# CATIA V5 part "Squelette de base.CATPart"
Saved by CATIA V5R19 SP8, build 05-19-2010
Part number: Squelette de base
Publications: "Point.1", "Point.2", "Point.3", "Point.4", "Plan.1", "Point.5", "Point.6", "Point.7", "Point.8", "Point.9", "Plan.2", "Point.10", "Point.11", "Plan.3", "Point.12", "Point.13", "Plan.4", "Point.14", "Plan.5", "Point.15", "Plan.6", "Plan.7", "Plan.8", "Plan.9", "Plan.10", "Plan.11", "Plan.12", "Point.16", "Point.17", "Point.18", "Plan.13", "Plan.14"
Bounding box of the stored display mesh (mm): x -18 to 0, y -9.5 to 15.5, z 0 to 22
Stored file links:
  C:\Users\ThinkMotion\Desktop\EU_thinkMotion\iao\IAO_MMS_Groupe3\jbuffard\jbuffard\Squelette de base.CATPart
  C:\Users\ThinkMotion\Desktop\EU_thinkMotion\iao\IAO_MMS_Groupe3\jbuffard\jbuffard\Mecanisme a coulisse a quatre elements de la griffe d'une camera.CATProduct
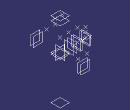
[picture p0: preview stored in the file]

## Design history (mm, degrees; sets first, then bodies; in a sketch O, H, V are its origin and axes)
External parameters (linked from other documents)
  `External.Hauteur pièce 2` = -0.02
  `External.Plan 6 bis` = 0.019
  `External.Augmentation hauteur` = 0
Set1
  Point1: type OnPlane, Support yz-plane, H -9.5, V 9, Direction (0, 1, 0)
  Point2: type OnPlane, Support yz-plane, H 0, V 9, Direction (0, 1, 0)
  Point3: type OnPlane, Support yz-plane, H 9.5, V 9, Direction (0, 1, 0)
  Point4: type OnPlane, Support yz-plane, H 12.5, V 2.5, Direction (0, 1, 0)
  Plane1: type Offset, RefPlane yz-plane, Offset -6
  Point5: type OnPlane, Support Plane1, H 9.5, V 8.5, Direction (0, 1, 0)
  Point6: type OnPlane, Support Plane1, H -9.5, V 12.5, Direction (0, 1, 0)
  Point7: type OnPlane, Support Plane1, H 9.5, V 9, Direction (0, 1, 0)
  Point8: type OnPlane, Support Plane1, H 12.5, V 2.5, Direction (0, 1, 0)
  Point9: type OnPlane, Support Plane1, H -9.5, V 9, Direction (0, 1, 0)
  Plane2: type Offset, RefPlane Plane1, Offset -5
  Point10: type OnPlane, Support Plane2, H -9.5, V 12.5, Direction (0, 1, 0)
  Point11: type OnPlane, Support Plane2, H 9.5, V 8.5, Direction (0, 1, 0)
  Plane3: type Offset, RefPlane Plane2, Offset -1
  Point12: type OnPlane, Support Plane3, H 0, V 0, Direction (0, 1, 0)
  Point13: type OnPlane, Support Plane3, H 0, V 9, Direction (0, 1, 0)
  Plane4: type Offset, RefPlane Plane3, Offset -5
  Point14: type OnPlane, Support Plane4, H 0, V 0, Direction (0, 1, 0)
  Plane5: type Offset, RefPlane Plane4, Offset -1
  Point15: type OnPlane, Support Plane5, H 0, V 0, Direction (0, 1, 0)
  Plane6: type Offset, RefPlane xy-plane, Offset 19 {= `External.Plan 6 bis`}
  Plane7: type Offset, RefPlane xy-plane, Offset 22
  Plane8: type Offset, RefPlane Plane7, Offset -52
  Plane9: type Offset, RefPlane zx-plane, Offset -15.5
  Plane10: type Offset, RefPlane zx-plane, Offset -17.5
  Plane11: type Offset, RefPlane zx-plane, Offset 15.5
  Plane12: type Offset, RefPlane zx-plane, Offset 17.5
  Point16: type OnPlane, Support Plane1, H 0, V 9, Direction (0, 1, 0)
  Point17: type OnPlane, Support Plane6, H -2, V 15.5, Direction (1, 0, 0)
  Point18: type OnPlane, Support Plane7, H -2, V 15.5, Direction (1, 0, 0)
  Plane13: type Offset, RefPlane Plane6, Offset -20 {= `External.Hauteur pièce 2` +`External.Augmentation hauteur`}
  Plane14: type Offset, RefPlane Plane1, Offset -2.5
Body1 (main body)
